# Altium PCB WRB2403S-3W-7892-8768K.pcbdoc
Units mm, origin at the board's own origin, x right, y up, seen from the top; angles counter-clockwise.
Board outline 23.7 x 14.8 mm, 2 copper layers (Top Layer, Bottom Layer), stack 0.78 mm thick; 27 components, 17 nets, 72 pads, 29 vias.
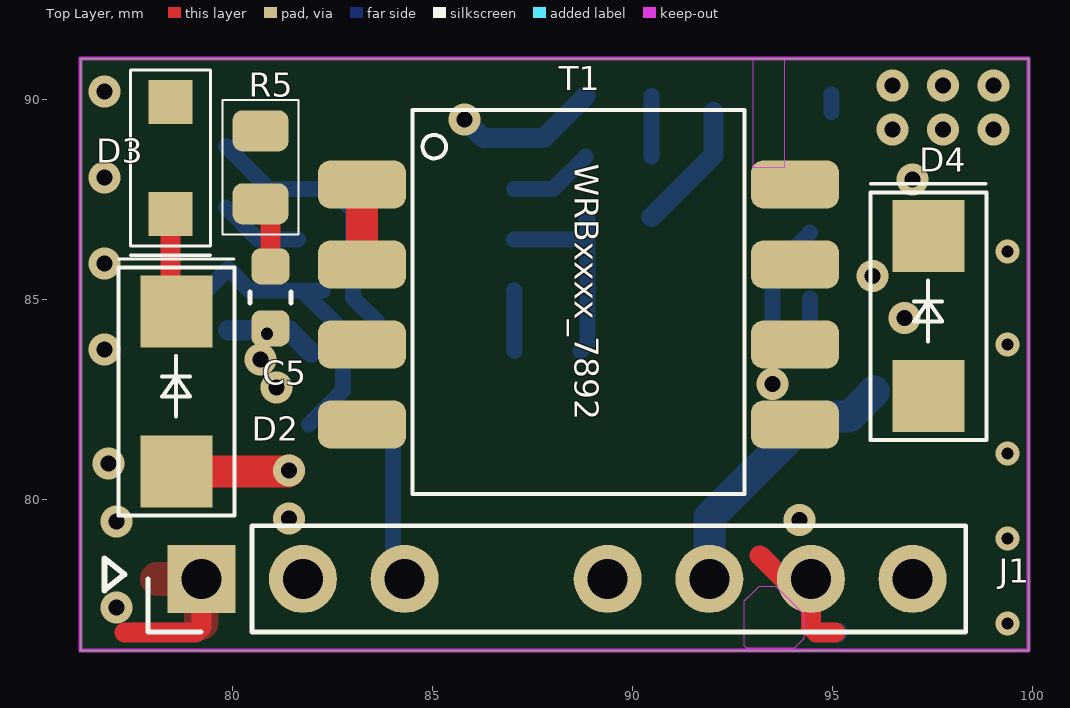
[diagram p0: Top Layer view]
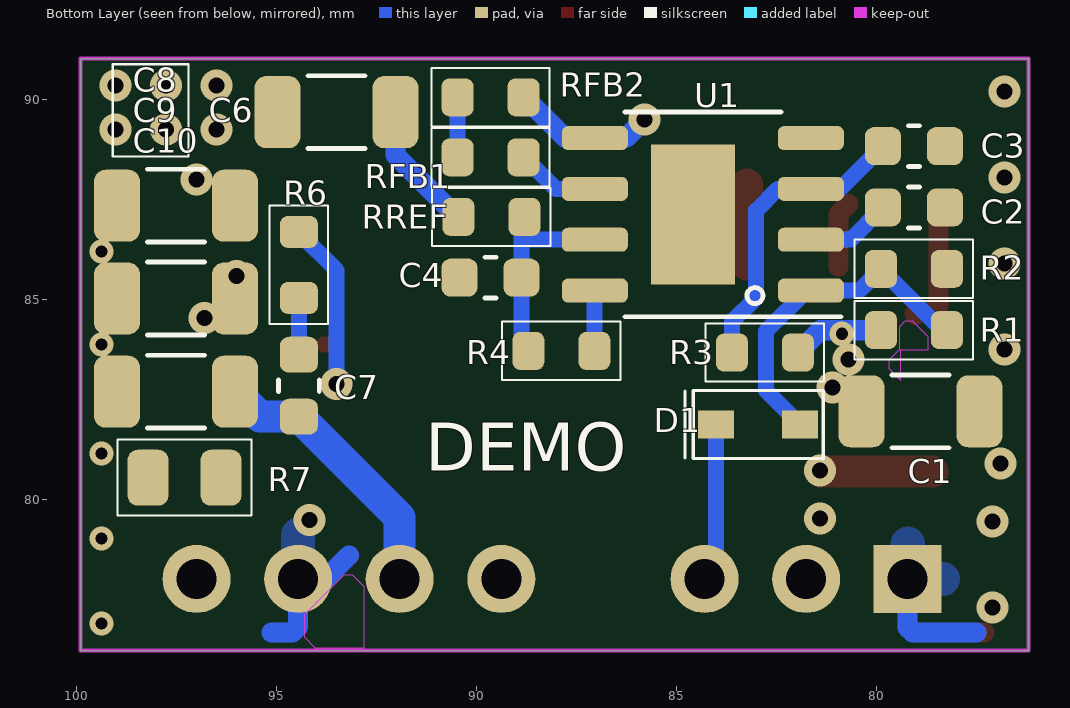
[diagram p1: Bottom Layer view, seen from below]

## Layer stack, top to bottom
Top Solder Mask Layer: solder mask 0.01, Dk 3.3
Top Layer: signal copper 0.035
Dielectric1: surface 0.71, FR4, Dk 4.5
Bottom Layer: signal copper 0.035
Bottom Solder Mask Layer: solder mask 0.01, Dk 3.3

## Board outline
76.2,91.02 99.9,91.02 99.9,76.22 76.2,76.22

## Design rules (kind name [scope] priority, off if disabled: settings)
BoardOutlineClearance safeClearance [All] p0: genericclearance=0.254 ignorepadtopadclearanceinfootprint=FALSE except(0: Arc-SplitContinuation Track-SplitContinuation SMDPad-SplitContinuation THPad-SplitContinuation Via-SplitContinuation Fill-SplitContinuation Poly-SplitContinuation Region-SplitContinuation Text-SplitContinuation)
BoardOutlineClearance Plane_innerPlane [All] p0: genericclearance=0.254 ignorepadtopadclearanceinfootprint=FALSE except(0: Arc-SplitContinuation Track-SplitContinuation SMDPad-SplitContinuation THPad-SplitContinuation Via-SplitContinuation Fill-SplitContinuation Poly-SplitContinuation Region-SplitContinuation Text-SplitContinuation)
BoardOutlineClearance Copper_CopperRegion [All] p0: genericclearance=0.254 ignorepadtopadclearanceinfootprint=FALSE except(0: Arc-SplitContinuation Track-SplitContinuation SMDPad-SplitContinuation THPad-SplitContinuation Via-SplitContinuation Fill-SplitContinuation Poly-SplitContinuation Region-SplitContinuation Text-SplitContinuation)
BoardOutlineClearance Copper_CopperRegion1 [All] p0: genericclearance=0.254 ignorepadtopadclearanceinfootprint=FALSE except(0: Arc-SplitContinuation Track-SplitContinuation SMDPad-SplitContinuation THPad-SplitContinuation Via-SplitContinuation Fill-SplitContinuation Poly-SplitContinuation Region-SplitContinuation Text-SplitContinuation)
BoardOutlineClearance Copper_CopperRegion2 [All] p0: genericclearance=0.254 ignorepadtopadclearanceinfootprint=FALSE except(0: Arc-SplitContinuation Track-SplitContinuation SMDPad-SplitContinuation THPad-SplitContinuation Via-SplitContinuation Fill-SplitContinuation Poly-SplitContinuation Region-SplitContinuation Text-SplitContinuation)
BoardOutlineClearance Copper_CopperRegion3 [All] p0: genericclearance=0.254 ignorepadtopadclearanceinfootprint=FALSE except(0: Arc-SplitContinuation Track-SplitContinuation SMDPad-SplitContinuation THPad-SplitContinuation Via-SplitContinuation Fill-SplitContinuation Poly-SplitContinuation Region-SplitContinuation Text-SplitContinuation)
BoardOutlineClearance Copper_CopperRegion4 [All] p0: genericclearance=0.254 ignorepadtopadclearanceinfootprint=FALSE except(0: Arc-SplitContinuation Track-SplitContinuation SMDPad-SplitContinuation THPad-SplitContinuation Via-SplitContinuation Fill-SplitContinuation Poly-SplitContinuation Region-SplitContinuation Text-SplitContinuation)
BoardOutlineClearance Copper_CopperRegion5 [All] p0: genericclearance=0.254 ignorepadtopadclearanceinfootprint=FALSE except(0: Arc-SplitContinuation Track-SplitContinuation SMDPad-SplitContinuation THPad-SplitContinuation Via-SplitContinuation Fill-SplitContinuation Poly-SplitContinuation Region-SplitContinuation Text-SplitContinuation)
BoardOutlineClearance Copper_CopperRegion6 [All] p0: genericclearance=0.254 ignorepadtopadclearanceinfootprint=FALSE except(0: Arc-SplitContinuation Track-SplitContinuation SMDPad-SplitContinuation THPad-SplitContinuation Via-SplitContinuation Fill-SplitContinuation Poly-SplitContinuation Region-SplitContinuation Text-SplitContinuation)
BoardOutlineClearance Copper_CopperRegion7 [All] p0: genericclearance=0.254 ignorepadtopadclearanceinfootprint=FALSE except(0: Arc-SplitContinuation Track-SplitContinuation SMDPad-SplitContinuation THPad-SplitContinuation Via-SplitContinuation Fill-SplitContinuation Poly-SplitContinuation Region-SplitContinuation Text-SplitContinuation)
BoardOutlineClearance Copper_CopperRegion8 [All] p0: genericclearance=0.254 ignorepadtopadclearanceinfootprint=FALSE except(0: Arc-SplitContinuation Track-SplitContinuation SMDPad-SplitContinuation THPad-SplitContinuation Via-SplitContinuation Fill-SplitContinuation Poly-SplitContinuation Region-SplitContinuation Text-SplitContinuation)
BoardOutlineClearance Copper_CopperRegion9 [All] p0: genericclearance=0.254 ignorepadtopadclearanceinfootprint=FALSE except(0: Arc-SplitContinuation Track-SplitContinuation SMDPad-SplitContinuation THPad-SplitContinuation Via-SplitContinuation Fill-SplitContinuation Poly-SplitContinuation Region-SplitContinuation Text-SplitContinuation)
BoardOutlineClearance Copper_CopperRegion10 [All] p0: genericclearance=0.254 ignorepadtopadclearanceinfootprint=FALSE except(0: Arc-SplitContinuation Track-SplitContinuation SMDPad-SplitContinuation THPad-SplitContinuation Via-SplitContinuation Fill-SplitContinuation Poly-SplitContinuation Region-SplitContinuation Text-SplitContinuation)
BoardOutlineClearance Copper_CopperRegion11 [All] p0: genericclearance=0.254 ignorepadtopadclearanceinfootprint=FALSE except(0: Arc-SplitContinuation Track-SplitContinuation SMDPad-SplitContinuation THPad-SplitContinuation Via-SplitContinuation Fill-SplitContinuation Poly-SplitContinuation Region-SplitContinuation Text-SplitContinuation)
BoardOutlineClearance Copper_CopperRegion12 [All] p0: genericclearance=0.254 ignorepadtopadclearanceinfootprint=FALSE except(0: Arc-SplitContinuation Track-SplitContinuation SMDPad-SplitContinuation THPad-SplitContinuation Via-SplitContinuation Fill-SplitContinuation Poly-SplitContinuation Region-SplitContinuation Text-SplitContinuation)
BoardOutlineClearance Copper_CopperRegion13 [All] p0: genericclearance=0.254 ignorepadtopadclearanceinfootprint=FALSE except(0: Arc-SplitContinuation Track-SplitContinuation SMDPad-SplitContinuation THPad-SplitContinuation Via-SplitContinuation Fill-SplitContinuation Poly-SplitContinuation Region-SplitContinuation Text-SplitContinuation)
BoardOutlineClearance Copper_CopperRegion14 [All] p0: genericclearance=0.254 ignorepadtopadclearanceinfootprint=FALSE except(0: Arc-SplitContinuation Track-SplitContinuation SMDPad-SplitContinuation THPad-SplitContinuation Via-SplitContinuation Fill-SplitContinuation Poly-SplitContinuation Region-SplitContinuation Text-SplitContinuation)
BoardOutlineClearance Copper_copperRegion1 [All] p0: genericclearance=0.254 ignorepadtopadclearanceinfootprint=FALSE except(0: Arc-SplitContinuation Track-SplitContinuation SMDPad-SplitContinuation THPad-SplitContinuation Via-SplitContinuation Fill-SplitContinuation Poly-SplitContinuation Region-SplitContinuation Text-SplitContinuation)
BoardOutlineClearance otherClearance [All] p0: genericclearance=0.254 ignorepadtopadclearanceinfootprint=FALSE except(0: Arc-SplitContinuation Track-SplitContinuation SMDPad-SplitContinuation THPad-SplitContinuation Via-SplitContinuation Fill-SplitContinuation Poly-SplitContinuation Region-SplitContinuation Text-SplitContinuation)
Clearance safeClearance [All] p1: gap=0.178 ignorepadtopadclearanceinfootprint=FALSE
Clearance Plane_innerPlane [All] p1: gap=0.178 ignorepadtopadclearanceinfootprint=FALSE
Clearance Copper_CopperRegion [All] p1: gap=0.178 ignorepadtopadclearanceinfootprint=FALSE
Clearance Copper_CopperRegion1 [All] p1: gap=0.178 ignorepadtopadclearanceinfootprint=FALSE
Clearance Copper_CopperRegion2 [All] p1: gap=0.178 ignorepadtopadclearanceinfootprint=FALSE
Clearance Copper_CopperRegion3 [All] p1: gap=0.178 ignorepadtopadclearanceinfootprint=FALSE
Clearance Copper_CopperRegion4 [All] p1: gap=0.178 ignorepadtopadclearanceinfootprint=FALSE
Clearance Copper_CopperRegion5 [All] p1: gap=0.178 ignorepadtopadclearanceinfootprint=FALSE
Clearance Copper_CopperRegion6 [All] p1: gap=0.178 ignorepadtopadclearanceinfootprint=FALSE
Clearance Copper_CopperRegion7 [All] p1: gap=0.178 ignorepadtopadclearanceinfootprint=FALSE
Clearance Copper_CopperRegion8 [All] p1: gap=0.178 ignorepadtopadclearanceinfootprint=FALSE
Clearance Copper_CopperRegion9 [All] p1: gap=0.178 ignorepadtopadclearanceinfootprint=FALSE
Clearance Copper_CopperRegion10 [All] p1: gap=0.178 ignorepadtopadclearanceinfootprint=FALSE
Clearance Copper_CopperRegion11 [All] p1: gap=0.178 ignorepadtopadclearanceinfootprint=FALSE
Clearance Copper_CopperRegion12 [All] p1: gap=0.178 ignorepadtopadclearanceinfootprint=FALSE
Clearance Copper_CopperRegion13 [All] p1: gap=0.178 ignorepadtopadclearanceinfootprint=FALSE
Clearance Copper_CopperRegion14 [All] p1: gap=0.178 ignorepadtopadclearanceinfootprint=FALSE
Clearance Copper_copperRegion1 [All] p1: gap=0.178 ignorepadtopadclearanceinfootprint=FALSE
Clearance otherClearance [All] p1: gap=0.178 ignorepadtopadclearanceinfootprint=FALSE
DiffPairsRouting differentialPair [All] p1: maxuncoupledlength=10 minlimit=6 maxlimit=Infinity mostfreqgap=6 toplayer_minwidth=5 toplayer_prefwidth=10 toplayer_maxwidth=100 bottomlayer_minwidth=5 bottomlayer_prefwidth=10 bottomlayer_maxwidth=100
PasteMaskExpansion Common [All] p1: expansion=0
PlaneConnect innerPlane [All] p1: planeconnectstyle=Relief reliefexpansion=0.508 reliefentries=4 reliefconductorwidth=0.254 reliefairgap=0.254
PolygonConnect CopperRegion [All] p1: connectstyle=Relief reliefentries=4 reliefconductorwidth=0 polygonreliefangle="90 Angle" airgapwidth=1
PolygonConnect CopperRegion1 [All] p1: connectstyle=Direct reliefentries=4 reliefconductorwidth=10 polygonreliefangle="90 Angle" airgapwidth=10
PolygonConnect CopperRegion2 [All] p1: connectstyle=Relief reliefentries=4 reliefconductorwidth=0 polygonreliefangle="90 Angle" airgapwidth=9.8425
PolygonConnect CopperRegion3 [All] p1: connectstyle=Relief reliefentries=4 reliefconductorwidth=0 polygonreliefangle="90 Angle" airgapwidth=1
PolygonConnect CopperRegion4 [All] p1: connectstyle=Relief reliefentries=4 reliefconductorwidth=0 polygonreliefangle="90 Angle" airgapwidth=1
PolygonConnect CopperRegion5 [All] p1: connectstyle=Relief reliefentries=4 reliefconductorwidth=0 polygonreliefangle="90 Angle" airgapwidth=1
PolygonConnect CopperRegion6 [All] p1: connectstyle=Relief reliefentries=4 reliefconductorwidth=0 polygonreliefangle="90 Angle" airgapwidth=1
PolygonConnect CopperRegion7 [All] p1: connectstyle=Relief reliefentries=4 reliefconductorwidth=0 polygonreliefangle="90 Angle" airgapwidth=1
PolygonConnect CopperRegion8 [All] p1: connectstyle=Relief reliefentries=4 reliefconductorwidth=0 polygonreliefangle="90 Angle" airgapwidth=1
PolygonConnect CopperRegion9 [All] p1: connectstyle=Relief reliefentries=4 reliefconductorwidth=0 polygonreliefangle="90 Angle" airgapwidth=1
PolygonConnect CopperRegion10 [All] p1: connectstyle=Relief reliefentries=4 reliefconductorwidth=0 polygonreliefangle="90 Angle" airgapwidth=1
PolygonConnect CopperRegion11 [All] p1: connectstyle=Relief reliefentries=4 reliefconductorwidth=0 polygonreliefangle="90 Angle" airgapwidth=1
PolygonConnect CopperRegion12 [All] p1: connectstyle=Relief reliefentries=4 reliefconductorwidth=0 polygonreliefangle="90 Angle" airgapwidth=1
PolygonConnect CopperRegion13 [All] p1: connectstyle=Relief reliefentries=4 reliefconductorwidth=0 polygonreliefangle="90 Angle" airgapwidth=1
PolygonConnect CopperRegion14 [All] p1: connectstyle=Relief reliefentries=4 reliefconductorwidth=0 polygonreliefangle="90 Angle" airgapwidth=1
PolygonConnect copperRegion1 [All] p1: connectstyle=Relief reliefentries=4 reliefconductorwidth=10 polygonreliefangle="90 Angle" airgapwidth=10
RoutingVias viaSize [All] p1: viastyle="Through Hole" holewidth=12.0078 minholewidth=11.811 maxholewidth=236.2204 width=12.0078 minwidth=11.811 maxwidth=236.2204
SolderMaskExpansion Common [All] p1: useseparateexpansions=TRUE expansion=0 expansionbottom=0
Width trackWidth [All] p1: maxlimit=100 minlimit=5 preferedwidth=10

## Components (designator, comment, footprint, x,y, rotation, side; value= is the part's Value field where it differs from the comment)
C1 "" C1206 78.9,82.2 r180 bottom
C2 "" C0603 79.065,87.297 r0 bottom
C3 "" C0603 79.065,88.83 r180 bottom
C4 "" C0603 89.65,85.543 r180 bottom
C5 "" C0603 80.95,85.05 r270 top
C6 "" C1206 93.5,89.68 r180 bottom
C7 "" coileasy:C_0603 94.44,82.84 r270 bottom
C8 "" coileasy:C_1206 97.515,87.34 r0 bottom
C9 "" C1206 97.515,85.02 r0 bottom
C10 "" C1206 97.515,82.69 r0 bottom
D1 "" SOD-323_L1.8-W1.3-LS2.5-RD 82.96,81.88 r180 bottom
D2 "" SMA_L4.3-W2.6-LS5.2-RD 78.6,82.7 r270 top
D3 "" SOD-123_L2.8-W1.8-LS3.7-FD 78.5,88.63 r90 top
D4 "" SMAF_L3.5-W2.6-LS4.7-RD 97.4,84.58 r270 top
J1 "Coileasy_Conn_01x07_1" coileasy:PinHeader_01x07_1_P2.54mm_Vertical 79.22,78.01 r90 top
R1 "" R0603 79.065,84.23 r0 bottom
R2 "" R0603 79.065,85.763 r0 bottom
R3 "" R0603 82.79,83.67 r180 bottom
R4 "" coileasy:R_0603 87.88,83.71 r0 bottom
R5 "" R0805#1 80.7,88.3 r90 top
R6 "" coileasy:R_0603 94.44,85.86 r90 bottom
R7 "" R0805#2 97.3,80.54 r0 bottom
RFB1 "" R0603 89.65,88.55 r180 bottom
RFB2 "" R0603 89.65,90.05 r0 bottom
RREF "" R0603 89.628,87.059 r180 bottom
T1 "MYLibrary _CMT_3+3" "coileasy:SMD-8P, 11.55x9.6, ER9.5 4+4" 88.652,84.93 r0 top
U1 "" ESOP-8_L4.9-W3.9-P1.27-LS6.0-BL-EP3.3 84.34,87.125 r0 bottom

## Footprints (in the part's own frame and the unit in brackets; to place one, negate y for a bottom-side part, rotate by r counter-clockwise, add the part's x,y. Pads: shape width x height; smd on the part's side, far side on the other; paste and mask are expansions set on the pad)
C0603 [mm]
  rrect50% 0.9x0.95 smd: 1(-0.775,0) 2(0.775,0)
  silkscreen extent -0.14,-0.51 0.14,0.51
C1206 [mm]
  rrect50% 1.15x1.8 smd: 1(-1.475,0) 2(1.475,0)
  silkscreen extent -0.71,-0.91 0.71,0.91
coileasy:C_0603 [mm]
  rrect50% 0.9x0.95 smd: 1(-0.775,0) 2(0.775,0)
  silkscreen extent -0.14,-0.51 0.14,0.51
coileasy:C_1206 [mm]
  rrect50% 1.15x1.8 smd: 1(-1.475,0) 2(1.475,0)
  silkscreen extent -0.71,-0.91 0.71,0.91
coileasy:PinHeader_01x07_1_P2.54mm_Vertical [mm]
  rect 1.7x1.7 hole 1: 1(0,0)
  round 1.7 hole 1: 2(0,-2.54) 3(0,-5.08) 5(0,-10.16) 6(0,-12.7) 7(0,-15.24) 8(0,-17.78)
  silkscreen extent -1.33,-19.11 1.33,1.33
coileasy:R_0603 [mm]
  rrect50% 0.8x0.95 smd: 1(-0.825,0) 2(0.825,0)
  silkscreen extent -1.48,-0.73 1.48,0.73
"coileasy:SMD-8P, 11.55x9.6, ER9.5 4+4" [mm]
  rrect50% 2.2x1.2 smd: 1(-5.412,2.94) 2(-5.412,0.94) 3(-5.412,-1.06) 4(-5.412,-3.06) 5(5.413,-3.06) 6(5.413,-1.06) 7(5.413,0.94) 8(5.413,2.94)
  silkscreen extent -4.15,-4.8 4.15,4.8
ESOP-8_L4.9-W3.9-P1.27-LS6.0-BL-EP3.3 [mm]
  rrect50% 1.65x0.6 smd: 1(-2.7,1.905) 2(-2.7,0.635) 3(-2.7,-0.635) 4(-2.7,-1.905) 5(2.7,-1.905) 6(2.7,-0.635) 7(2.7,0.635) 8(2.7,1.905)
  rect 2.1x3.5 smd: 9(0.25,0)
  silkscreen extent -3.45,-2.56 1.95,2.56
R0603 [mm]
  rrect50% 0.8x0.95 smd: 1(-0.825,0) 2(0.825,0)
  silkscreen extent -1.48,-0.73 1.48,0.73
R0805#1 [mm]
  rrect48% 1.025x1.4 smd: 1(-0.913,0) 2(0.913,0)
  silkscreen extent -1.68,-0.95 1.68,0.95
R0805#2 [mm]
  rrect50% 1.025x1.4 smd: 1(-0.913,0) 2(0.913,0)
  silkscreen extent -1.68,-0.95 1.68,0.95
SMA_L4.3-W2.6-LS5.2-RD [mm]
  rect 1.8x1.8 smd: 1(-2,0) 2(2,0)
  silkscreen extent -3.31,-1.45 3.1,1.45
SMAF_L3.5-W2.6-LS4.7-RD [mm]
  rect 1.8x1.8 smd: 1(-2,0) 2(2,0)
  silkscreen extent -3.31,-1.45 3.1,1.45
SOD-123_L2.8-W1.8-LS3.7-FD [mm]
  rect 1.1x1.1 smd: 1(-1.5,0.05) 2(1.3,0.05)
  silkscreen extent -2.53,-0.95 2.1,1.05
SOD-323_L1.8-W1.3-LS2.5-RD [mm]
  rect 0.9x0.7 smd: 1(-1.05,-0.01) 2(1.05,-0.01)
  silkscreen extent -1.83,-0.86 1.63,0.84

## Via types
v1: diameter 0.8, hole 0.4, Top Layer to Bottom Layer, 23 vias
v2: diameter 0.6, hole 0.3, Top Layer to Bottom Layer, 5 vias
v3: diameter 0.61, hole 0.305, Top Layer to Bottom Layer, 1 vias

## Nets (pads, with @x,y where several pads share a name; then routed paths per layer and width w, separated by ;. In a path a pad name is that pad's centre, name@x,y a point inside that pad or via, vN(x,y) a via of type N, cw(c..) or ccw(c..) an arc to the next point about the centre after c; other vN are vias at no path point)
$1N2: D4.2 R6.2 T1.5 T1.6 | length 4.5
  Top Layer w0.4: T1.6@93.52,83.87 T1.6@93.815,83.87
  Bottom Layer w0.4: v1(93.5,82.88) 93.5,85.725 R6.2@94.44,86.665
$1N4: C5.1 R5.1 | length 1.7
  Top Layer w0.5: R5.1 80.95,87.138 C5.1
$1N11: C2.2 U1.2 | length 2.1
  Bottom Layer w0.4: C2.2 80.647,86.49 U1.2
$1N13: C3.1 R3.1 U1.3 | length 7.6
  Bottom Layer w0.4: C3.1 80.91,87.76 U1.3 82.465,87.76 83.01,87.215 83.01,85.04 83.615,84.435 R3.1
$1N26: RFB1.1 RFB2.2 | length 1.5
  Bottom Layer w0.4: RFB1.1@90.475,88.568 RFB2.2@90.475,90.08
$1N479: C7.1 R6.1 | length 1.4
  Bottom Layer w0.4: C7.1 R6.1@94.44,85.015
$1N482: D2.1 D3.1 | length 2.5
  Top Layer w0.5: D3.1 78.45,84.85 D2.1 ; D2.1@79.02,84.61 D2.1@79.05,84.64
$1N487: R4.1 U1.8 | length 1.5
  Bottom Layer w0.4: U1.8 87.055,85.205 R4.1
CTRL: D1.1 J1.3 | length 4
  Bottom Layer w0.4: D1.1 84.01,78.27 J1.3@84.3,77.98
EN: D1.2 R1.1 R2.2 U1.1 | length 9
  Bottom Layer w0.4: R1.1 78.357,84.23 R2.2 80.433,85.22 U1.1 U1.1@81.745,85.22 ; D1.2 82.766,82.726 82.766,84.199 U1.1@81.745,85.22 ; U1.1@82.26,85.22 U1.1@81.745,85.22
GND1: C1.2 C2.1 C3.2 C4.1 C6.2 J1.1 R2.1 RREF.1 U1.4 U1.9 | length 9.4
  Top Layer w0.5: 77.3,76.671 79.071,76.671 79.22,76.82 J1.1@79.22,77.98
  Bottom Layer w0.5: 77.5,76.671 79.1,76.671 79.22,76.791 J1.1@79.22,77.98 ; RREF.1@90.475,87.055 92.025,88.605 C6.2
  other v1: 77.1,77.3 77.1,79.45 76.9,80.9 76.8,83.75 76.8,85.9 76.8,88.05 76.8,90.2
GND2: C6.1 C8.2 C9.2 C10.2 J1.7 R7.2 T1.7 T1.8 | length 7.3
  Top Layer w0.5: 93.18,78.6 93.77,78.01 J1.7 94.46,76.808 94.597,76.671 95.07,76.671
  Bottom Layer w0.4: C6.1 C6.1@94.975,90.115
  Bottom Layer w0.5: 93.19,78.6 93.78,78.01 J1.7 94.46,76.808 94.597,76.671 95.12,76.671
  other v1: 94.17,79.48 96.5,89.25 97.76,89.25 99.02,89.25 96.5,90.35 97.76,90.35 99.02,90.35
  other v2: 99.38,76.9 99.38,79.02 99.38,81.14 99.38,83.87 99.38,86.19
RFB: RFB1.2 U1.6 | length 2.1
  Bottom Layer w0.4: U1.6 88.017,87.76 RFB1.2@88.825,88.568
RREF: C4.2 R4.2 RREF.2 U1.7 | length 5.3
  Bottom Layer w0.4: U1.7 88.865,86.49 88.875,86.48 ; R4.2 88.875,83.88 C4.2 88.875,86.48 ; RREF.2@88.825,87.055 88.875,87.005 88.875,86.48
SW: D3.2 R5.2 RFB2.1 T1.1 T1.2 U1.5 | length 5.7
  Top Layer w0.8: T1.2 T1.1
  Bottom Layer w0.5: v1(85.8,89.5) 86.27,89.03 U1.5 87.775,89.03 RFB2.1@88.825,90.08
VIN: C1.1 C5.2 D2.2 J1.2 R1.2 R3.2 T1.3 T1.4 | length 5.3
  Top Layer w0.8: D2.2 81.39,80.7 v1(81.41,80.72)
  Bottom Layer w0.508: R1.2 v3@80.773,84.23 ; v3(80.865,84.138) v3@80.773,84.23 ; R3.2 81.405,84.23 v3@80.773,84.23
  other v1: 81.41,79.52 81.1,82.8 80.7,83.5
VOUT: C7.2 C8.1 C9.1 C10.1 D4.1 J1.6 R7.1 | length 7
  Bottom Layer w0.8: J1.6@91.92,77.95 91.92,79.545 C7.2 95.415,82.065 C10.1
  other v1: 96.8,84.53 96,85.58 97,87.99
pads on no net: J1.5 J1.8

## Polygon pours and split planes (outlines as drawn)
GND2 on Bottom Layer (solid, remove dead copper, pour order 16): 99.9,80 99.9,76.2 92.9,76.2 92.81,76.29 92.81,79.23 93.58,80 99.7,80
GND1 on Top Layer (solid, remove dead copper, pour order 0): 76.2,78.868 76.2,91 77.513,91 77.5,86 77.5,79.425 80.1,79.425 80.1,78.818
GND1 on Top Layer (solid, remove dead copper, pour order 2): 76.2,79.2 80.1,79.2 80.1,76.2 76.2,76.2
GND1 on Bottom Layer (solid, remove dead copper, pour order 18): 76.2,80.3 80.1,80.3 80.1,76.2 76.2,76.2
GND2 on Top Layer (solid, remove dead copper, pour order 4): 95.2,85.3 95.2,88.24 95.8,88.24 95.8,90.8 93,90.8 93,85.3
GND2 on Bottom Layer (solid, remove dead copper, pour order 20): 94.4,91 99.9,91 99.9,79.8 99.9,79.7 97.9,79.7 97.9,88.6 94.4,88.6
VOUT on Bottom Layer (solid, remove dead copper, pour order 22): 97.25,79.85 97.25,88.44 95.33,88.44 95.33,79.85
VOUT on Top Layer (solid, remove dead copper, pour order 6): 95.35,83.83 95.35,88.46 98.8,88.46 98.8,83.83
$1N2 on Top Layer (solid, remove dead copper, pour order 8): 92.9,81.43 92.9,83.63 98.8,83.63 98.8,81.43
SW on Top Layer (solid, remove dead copper, pour order 10): 77.9,90.455 86.35,90.455 86.35,88.63 84.275,88.63 84.275,87.23 82.6,87.23 82.6,88.68 77.9,88.68
GND1 on Bottom Layer (solid, remove dead copper, pour order 24): 85.64,86.5 85.64,82.88 85.65,82.88 87.51,82.88 89.39,82.88 89.9,83.4 89.9,87.6 90.9,87.6 90.9,82.5 90.4,82 84.7,82 84.6,82.1 84.6,84.1 84.3,84.4 84.2,84.4 83.54,85.06 83.54,86.5
GND2 on Top Layer (solid, remove dead copper, pour order 12): 93,85.53 93,90.98 99.9,90.98 99.9,76.2 92.9,76.2
GND1 on Bottom Layer (solid, remove dead copper, pour order 26): 80.1,80 80.1,88.7 82.4,88.7 83.1,88 85.2,88 85.3,88.1 85.3,91 76.2,91 76.2,80
VIN on Bottom Layer (solid, remove dead copper, pour order 28): 80.4,76.3 80.4,81.5 79.5,81.5 79.5,84.6 79.6,84.7 82.2,84.7 82.6,84.3 82.6,76.2 80.5,76.2
VIN on Top Layer (solid, remove dead copper, pour order 14): 82.6,76.2 82.6,81 84.4,81 84.4,84.5 80.4,84.5 80.4,76.2 80.5,76.2

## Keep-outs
Top Layer:
  region: 93,88.3 93.8,88.3 93.8,91 93,91
  region: 93.58,77.83 94.28,77.13 94.28,76.52 94.04,76.28 92.85,76.28 92.79,76.34 92.79,77.46 92.89,77.56 92.89,77.55 93.17,77.83
Bottom Layer:
  region: 78.72,83.73 79.42,83.73 79.42,84.32 79.28,84.46 79.105,84.46 78.72,84.075
  region: 79.39,82.98 79.39,83.73 79.44,83.73 79.69,83.48 79.69,83.28
  region: 93.326,78.104 94.31,77.12 94.31,76.56 94.04,76.29 92.81,76.29 92.81,77.821 93.093,78.104
Board Outline Layer:
  the board outline again, w0.1

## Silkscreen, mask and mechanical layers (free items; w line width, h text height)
Top Silkscreen Layer:
  lines w0.15: 76.8,77.725 76.8,78.525 77.3,78.125 76.8,77.725
  text "WRBxxxx_7892" at 88.56,88.39 h0.6 r270
Bottom Silkscreen Layer:
  lines w0.06: 97.2,88.57 99.09,88.57 99.09,90.88 97.2,90.88 97.2,88.57
  text "DEMO" at 91.283,80.71 h1.2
